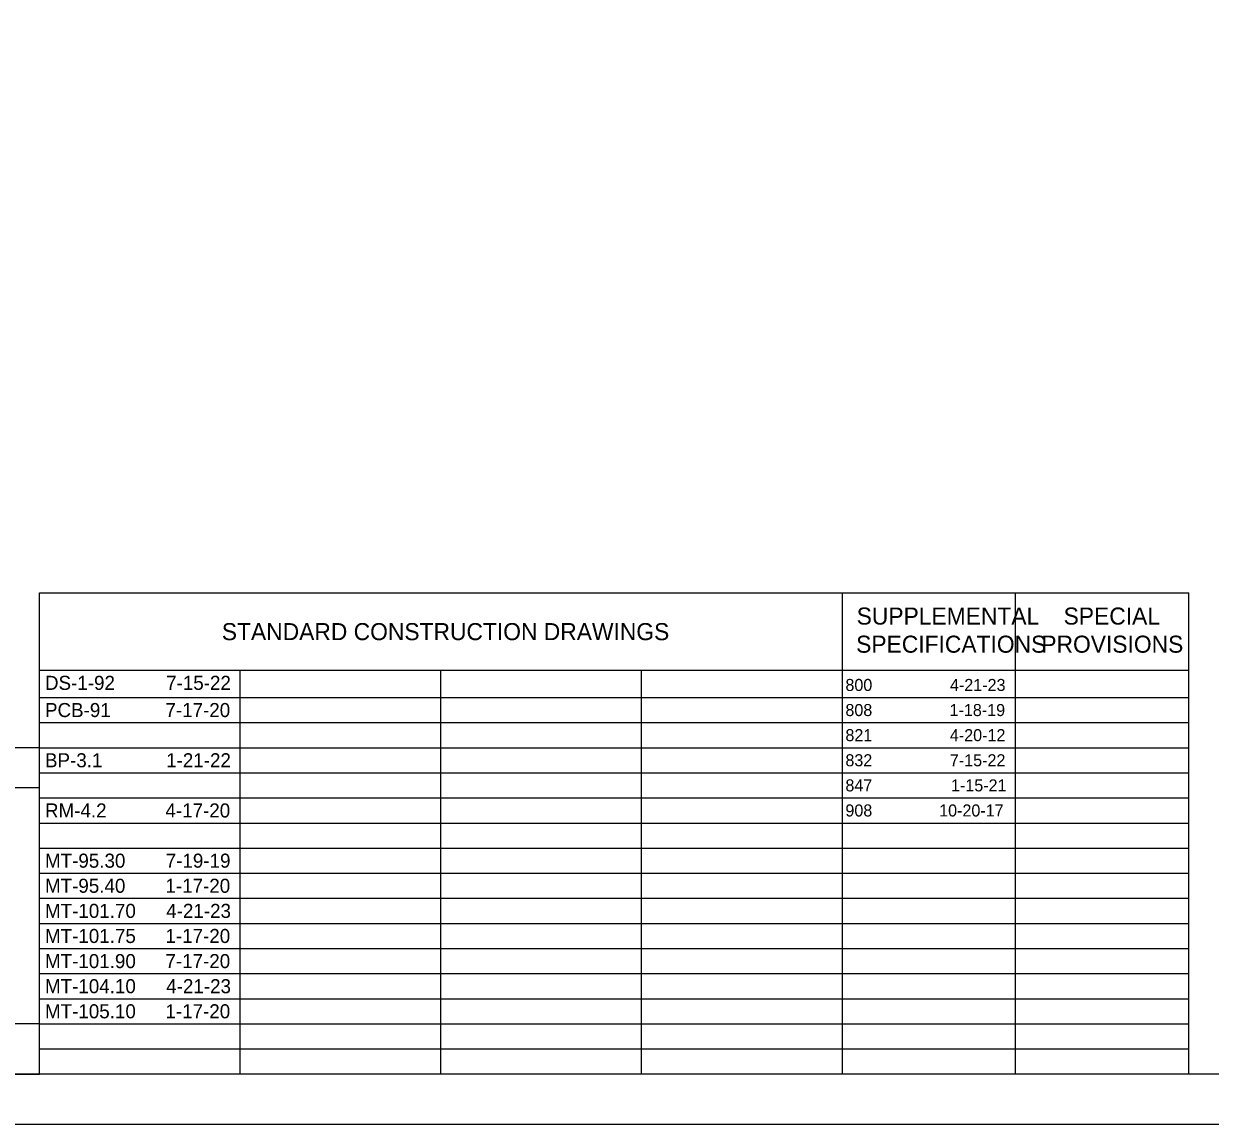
# Model space of a CAD drawing. Extents: x 39.8 to 73.8, y 13 to 35.
# Drawn here: x 52.23 to 64.06, y 12.96 to 23.92 of the extents above; entities that cross this region are included whole.
import ezdxf

# ---------------------------------------------------------------- set-up
doc = ezdxf.new("R2010")
doc.units = 0
for name, color, linetype in [('SH_Border', 7, 'Continuous'), ('SH_Cut_Line', 7, 'Continuous'), ('SH_Data', 7, 'Continuous'), ('SH_Text', 7, 'Continuous')]:
    doc.layers.add(name, color=color, linetype=linetype)

msp = doc.modelspace()

# ---------------------------------------------------------------- linework, layer by layer
at = {"layer": 'SH_Border'}
msp.add_lwpolyline([(41.263, 34.465), (73.263, 34.465), (73.263, 13.465), (41.263, 13.465)], close=True, dxfattribs=at)
at = {"layer": 'SH_Cut_Line'}
msp.add_lwpolyline([(39.763, 12.965), (73.763, 12.965), (73.763, 34.965), (39.763, 34.965)], close=True, dxfattribs=at)
at = {"layer": 'SH_Data'}
for p, q in [((52.39, 18.257), (63.84, 18.257)), ((52.39, 13.465), (52.39, 18.257)), ((60.39, 13.465), (60.39, 18.257)), ((62.115, 13.465), (62.115, 18.257)), ((63.84, 13.465), (63.84, 18.257)), ((52.39, 17.486), (63.84, 17.486)), ((54.39, 13.465), (54.39, 17.486)), ((56.39, 13.465), (56.39, 17.486)), ((58.39, 13.465), (58.39, 17.486)), ((52.39, 17.215), (63.84, 17.215)), ((52.39, 16.965), (63.84, 16.965)), ((52.39, 16.715), (49.59, 16.715)), ((52.39, 16.715), (63.84, 16.715)), ((52.39, 13.465), (52.39, 16.715)), ((52.39, 16.465), (63.84, 16.465)), ((52.39, 16.315), (49.59, 16.315)), ((52.39, 16.215), (63.84, 16.215)), ((52.39, 15.965), (63.84, 15.965)), ((52.39, 15.715), (63.84, 15.715)), ((52.39, 15.465), (63.84, 15.465)), ((52.39, 15.215), (63.84, 15.215)), ((52.39, 14.965), (63.84, 14.965)), ((52.39, 14.715), (63.84, 14.715)), ((52.39, 14.465), (63.84, 14.465)), ((52.39, 14.215), (63.84, 14.215)), ((52.39, 13.965), (63.84, 13.965)), ((52.39, 13.715), (63.84, 13.715)), ((52.39, 13.465), (49.59, 13.465))]:
    msp.add_line(p, q, dxfattribs=at)
msp.add_lwpolyline([(52.39, 13.465), (52.39, 13.965), (49.59, 13.965), (49.59, 13.465)], close=True, dxfattribs=at)

# ---------------------------------------------------------------- texts
at = {"layer": 'SH_Text'}
for s, height, p in [('SUPPLEMENTAL', 0.17, (60.532, 17.941)), ('SPECIAL', 0.17, (62.594, 17.941)), ('STANDARD CONSTRUCTION DRAWINGS', 0.17, (54.207, 17.786)), ('SPECIFICATIONS', 0.17, (60.527, 17.661)), ('PROVISIONS', 0.17, (62.372, 17.661)), ('DS-1-92', 0.14, (52.445, 17.291)), ('7-15-22', 0.14, (53.652, 17.291)), ('800', 0.12, (60.42, 17.28)), ('4-21-23', 0.12, (61.462, 17.28)), ('PCB-91', 0.14, (52.445, 17.02)), ('7-17-20', 0.14, (53.645, 17.02)), ('808', 0.12, (60.42, 17.03)), ('1-18-19', 0.12, (61.458, 17.03)), ('821', 0.12, (60.42, 16.78)), ('4-20-12', 0.12, (61.461, 16.78)), ('BP-3.1', 0.14, (52.445, 16.52)), ('1-21-22', 0.14, (53.652, 16.52)), ('832', 0.12, (60.42, 16.53)), ('7-15-22', 0.12, (61.461, 16.53)), ('847', 0.12, (60.42, 16.28)), ('1-15-21', 0.12, (61.472, 16.28)), ('RM-4.2', 0.14, (52.445, 16.02)), ('4-17-20', 0.14, (53.645, 16.02)), ('908', 0.12, (60.42, 16.03)), ('10-20-17', 0.12, (61.354, 16.03)), ('MT-95.30', 0.14, (52.445, 15.52)), ('7-19-19', 0.14, (53.648, 15.52)), ('MT-95.40', 0.14, (52.445, 15.27)), ('1-17-20', 0.14, (53.645, 15.27)), ('MT-101.70', 0.14, (52.445, 15.02)), ('4-21-23', 0.14, (53.653, 15.02)), ('MT-101.75', 0.14, (52.445, 14.77)), ('1-17-20', 0.14, (53.645, 14.77)), ('MT-101.90', 0.14, (52.445, 14.52)), ('7-17-20', 0.14, (53.645, 14.52)), ('MT-104.10', 0.14, (52.445, 14.27)), ('4-21-23', 0.14, (53.653, 14.27)), ('MT-105.10', 0.14, (52.445, 14.02)), ('1-17-20', 0.14, (53.645, 14.02))]:
    msp.add_text(s, height=height, dxfattribs=at).set_placement(p)

doc.saveas('drawing.dxf')
